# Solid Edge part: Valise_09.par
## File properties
Author: Bernard DUMAS
Template: Normal.par
Last saved by: FR026244
Revision: 15
Application: Solid Edge
Densité: 460.000 kg/m^3
Précision: 0.9900
Document Number: 09
Revision: a
Project Name: Slamson
Material: Bois, Frêne
Style de face: Jaune kaki
Style de remplissage: Liège
Style virtuel: Frêne verni
Coef. of Thermal Exp: 0.0
Thermal Conductivity: 0.0
Specific Heat: 0.0
Modulus of Elasticity: 0.0
Poission's Ratio: 0.0
Yield Stress: 0.0
Ultimate Stress: 0.0
Elongation: 0.0
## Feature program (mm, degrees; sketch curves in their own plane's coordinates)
sketch for "unnamed Protrusion 1" plane through (0, 0, 0) normal (0, 0, 1) x-axis (1, 0, 0)
extrude "unnamed Protrusion 1" add finite 5 along +normal
fillet "Congé_1" radius 5
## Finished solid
Body 1: solid body, 6 faces, 12 edges, 8 vertices.
  Faces by surface: plane 4, cylinder 2
  Edges by curve: line 8, circle 4
Bounding box of the edges (mm): 498.000 x 20.000 x 5.000, from (-249, -10, 0) to (249, 10, 5).
Cylindrical faces by radius (mm): R5 x2
Planar faces by outward normal: +y 1, +z 1, -y 1, -z 1
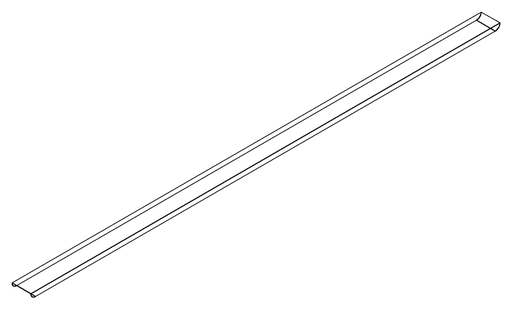
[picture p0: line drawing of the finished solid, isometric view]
